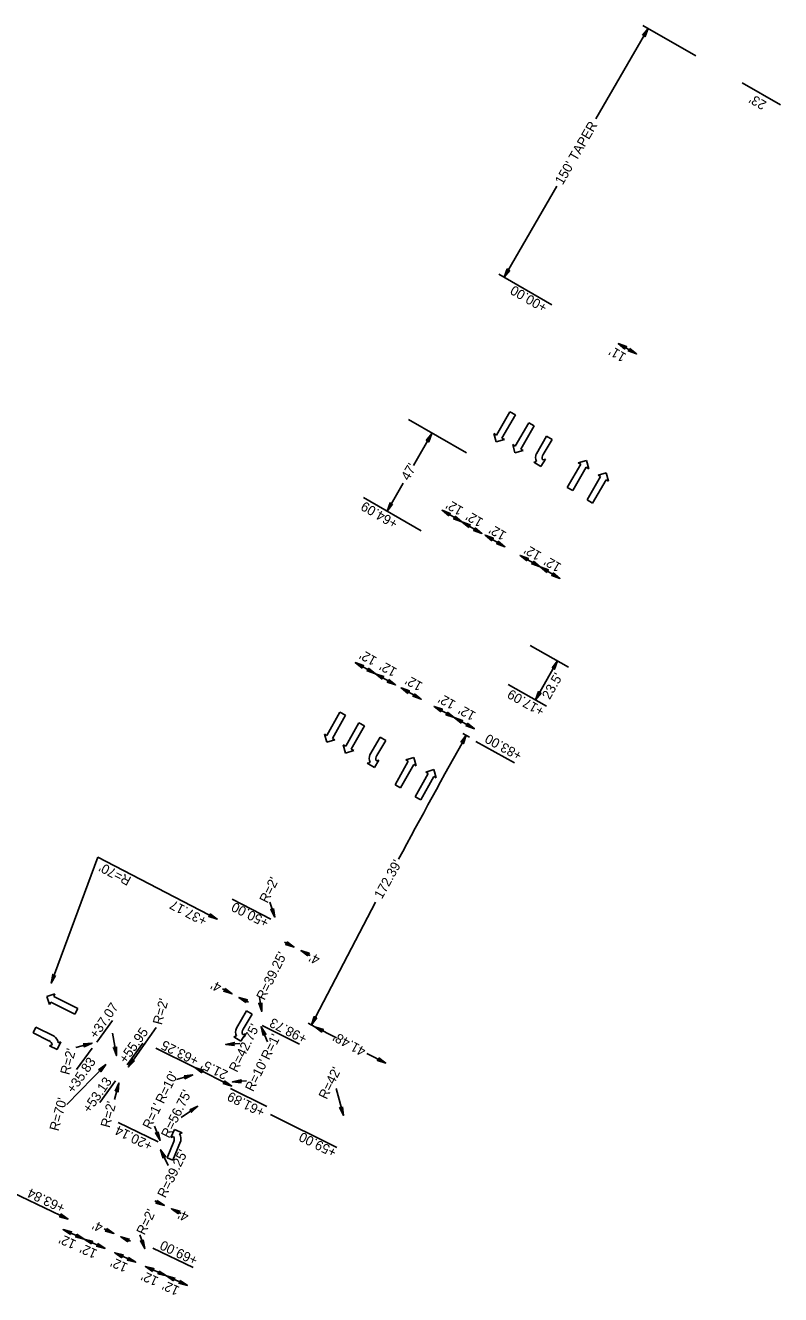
# Model space of a CAD drawing. Extents: x 2320991 to 2332664, y 598057 to 612602.
# Drawn here: x 2328874 to 2329267, y 607916 to 608578 of the extents above; entities that cross this region are included whole.
import ezdxf

# ---------------------------------------------------------------- set-up
doc = ezdxf.new("R2010")
doc.units = 0
for name, color, linetype in [('Prop Dimension', 7, 'Continuous'), ('Prop Dimension Text', 7, 'Continuous'), ('Prop Lane Arrow CELL', 7, 'Continuous'), ('Prop Terminator CELL', 7, 'Continuous')]:
    doc.layers.add(name, color=color, linetype=linetype)

msp = doc.modelspace()

# ---------------------------------------------------------------- linework, layer by layer
at = {"layer": 'Prop Dimension'}
for p, q in [((2329223.25, 608562.07), (2329195.67, 608578.01)), ((2329171.09, 608529.31), (2329198.34, 608576.46)), ((2329247.48, 608548.05), (2329267.44, 608536.61)), ((2329123.38, 608446.76), (2329150.83, 608494.25)), ((2329148.28, 608432.37), (2329120.61, 608448.36)), ((2329182.81, 608412.17), (2329192.38, 608406.74)), ((2329103.69, 608355.21), (2329073.58, 608372.62)), ((2329085.64, 608365.19), (2329076.05, 608348.63)), ((2329070.73, 608339.37), (2329062.32, 608324.84)), ((2329080.17, 608314.52), (2329050.06, 608331.92)), ((2329101.37, 608319.21), (2329090.98, 608325.22)), ((2329111.76, 608313.2), (2329101.37, 608319.21)), ((2329123.8, 608306.26), (2329113.41, 608312.27)), ((2329142.08, 608295.73), (2329131.69, 608301.73)), ((2329152.47, 608289.72), (2329142.08, 608295.73)), ((2329156.97, 608243.48), (2329136.96, 608254.79)), ((2329151.21, 608246.69), (2329139.71, 608226.39)), ((2329056.28, 608240.03), (2329045.8, 608245.87)), ((2329066.76, 608234.19), (2329056.28, 608240.03)), ((2329145.49, 608223.17), (2329125.43, 608234.51)), ((2329080.17, 608226.77), (2329069.69, 608232.61)), ((2329097.36, 608217.2), (2329086.88, 608223.04)), ((2329107.85, 608211.36), (2329097.36, 608217.2)), ((2329105.39, 608206.96), (2329101.89, 608208.9)), ((2329108.69, 608204.67), (2329128.73, 608193.52)), ((2328887.3, 608078.74), (2328911.68, 608144.36)), ((2328973.82, 608112.12), (2328911.68, 608144.36)), ((2329001.71, 608112.11), (2328981.67, 608122.58)), ((2329003.89, 608113.15), (2329001.28, 608120.91)), ((2329008.93, 608100.11), (2329013.86, 608097.56)), ((2329017.42, 608095.73), (2329022.34, 608093.19)), ((2328976.66, 608075.71), (2328981.6, 608073.17)), ((2328985.15, 608071.33), (2328990.07, 608068.79)), ((2328997, 608063.97), (2328995.84, 608071.31)), ((2328927.52, 608035.05), (2328941.98, 608055.64)), ((2328996.73, 608055.98), (2329000.08, 608048.07)), ((2328997.34, 608056.7), (2329016.68, 608046.86)), ((2329024.76, 608055.99), (2329021.19, 608057.81)), ((2329035.92, 608050.27), (2329024.76, 608055.99)), ((2328921.31, 608040.95), (2328919.33, 608052.61)), ((2328908.61, 608047.52), (2328900.07, 608045.23)), ((2328962.16, 608034.71), (2328941.93, 608044.83)), ((2328985.57, 608047.22), (2328978.24, 608046.79)), ((2329061.68, 608037.08), (2329051.83, 608042.12)), ((2328915.71, 608036.33), (2328895.51, 608015.54)), ((2328962.15, 608034.71), (2328981.38, 608025.1)), ((2328961.12, 608030.87), (2328952.58, 608028.57)), ((2328922.57, 608026.65), (2328920.27, 608018.11)), ((2328980.78, 608023.88), (2328999.73, 608014.41)), ((2328981.77, 608027.25), (2328989.12, 608027.74)), ((2329039.58, 608009.76), (2329035.78, 608023.87)), ((2328963.66, 608014.6), (2328955.03, 608008.77)), ((2329001.64, 608010.25), (2329036.09, 607993.06)), ((2328943, 607995.99), (2328922.25, 608006.15)), ((2328944.08, 607996.8), (2328941.07, 608004.18)), ((2328944.32, 607991.86), (2328948.3, 607983.7)), ((2328896.13, 607955.8), (2328832.86, 607985.72)), ((2328941.34, 607965.24), (2328946.35, 607962.85)), ((2328949.96, 607961.13), (2328954.96, 607958.74)), ((2328904.46, 607945.35), (2328893.51, 607950.27)), ((2328914.94, 607950.66), (2328919.96, 607948.27)), ((2328915.4, 607940.43), (2328904.46, 607945.35)), ((2328923.57, 607946.55), (2328928.57, 607944.17)), ((2328936.1, 607940.38), (2328933.47, 607947.49)), ((2328931.36, 607933.25), (2328920.42, 607938.17)), ((2328940.21, 607940.55), (2328961.3, 607930.49)), ((2328947.34, 607926.12), (2328936.4, 607931.04)), ((2328958.29, 607921.2), (2328947.34, 607926.12))]:
    msp.add_line(p, q, dxfattribs=at)
for start, end in [(150.90484, 151.75661), (152.04941, 152.88421)]:
    msp.add_arc((2333432.95, 605798.75), 4954.5, start, end, dxfattribs=at)
at = {"layer": 'Prop Dimension Text'}
for p, q in [((2328919.31, 608059.21), (2328911.18, 608048.01)), ((2328908.7, 608044.91), (2328900.57, 608033.71)), ((2328935.07, 608047.44), (2328926.94, 608036.24)), ((2328920.78, 608027.75), (2328912.64, 608016.55))]:
    msp.add_line(p, q, dxfattribs=at)
at = {"layer": 'Prop Lane Arrow CELL'}
for p, q in [((2329119.37, 608364.48), (2329126.41, 608376.58)), ((2329129.26, 608374.92), (2329122.22, 608362.82)), ((2329126.41, 608376.58), (2329129.26, 608374.92)), ((2329129.13, 608358.74), (2329136.17, 608370.84)), ((2329139.02, 608369.18), (2329131.98, 608357.08)), ((2329136.17, 608370.84), (2329139.02, 608369.18)), ((2329119.25, 608360.9), (2329118.07, 608365.23)), ((2329118.07, 608365.23), (2329119.37, 608364.48)), ((2329123.52, 608362.06), (2329119.25, 608360.9)), ((2329122.22, 608362.82), (2329123.52, 608362.06)), ((2329129.01, 608355.16), (2329127.83, 608359.49)), ((2329127.83, 608359.49), (2329129.13, 608358.74)), ((2329145.51, 608363.83), (2329140.15, 608354.74)), ((2329143.71, 608354.27), (2329148.35, 608362.16)), ((2329148.35, 608362.16), (2329145.51, 608363.83)), ((2329133.28, 608356.33), (2329129.01, 608355.16)), ((2329131.98, 608357.08), (2329133.28, 608356.33)), ((2329140.21, 608350.71), (2329138.77, 608350.33)), ((2329138.77, 608350.33), (2329142.54, 608348.06)), ((2329142.54, 608348.06), (2329144.87, 608351.91)), ((2329144.87, 608351.91), (2329143.43, 608351.54)), ((2329156.26, 608337.2), (2329163.3, 608349.3)), ((2329166.15, 608347.64), (2329159.11, 608335.54)), ((2329162, 608350.06), (2329166.27, 608351.22)), ((2329163.3, 608349.3), (2329162, 608350.06)), ((2329167.45, 608346.89), (2329166.15, 608347.64)), ((2329166.27, 608351.22), (2329167.45, 608346.89)), ((2329166.61, 608330.69), (2329173.65, 608342.79)), ((2329176.5, 608341.13), (2329169.46, 608329.03)), ((2329172.35, 608343.54), (2329176.61, 608344.71)), ((2329173.65, 608342.79), (2329172.35, 608343.54)), ((2329177.8, 608340.37), (2329176.5, 608341.13)), ((2329176.61, 608344.71), (2329177.8, 608340.37)), ((2329159.11, 608335.54), (2329156.26, 608337.2)), ((2329169.46, 608329.03), (2329166.61, 608330.69)), ((2329030.97, 608207.87), (2329037.81, 608220.08)), ((2329037.81, 608220.08), (2329040.69, 608218.47)), ((2329040.69, 608218.47), (2329033.85, 608206.26)), ((2329040.83, 608202.29), (2329047.66, 608214.51)), ((2329047.66, 608214.51), (2329050.54, 608212.9)), ((2329030.92, 608204.29), (2329029.66, 608208.6)), ((2329029.66, 608208.6), (2329030.97, 608207.87)), ((2329050.54, 608212.9), (2329043.71, 608200.68)), ((2329058.79, 608206.89), (2329053.43, 608197.8)), ((2329061.63, 608205.22), (2329058.79, 608206.89)), ((2329035.16, 608205.52), (2329030.92, 608204.29)), ((2329033.85, 608206.26), (2329035.16, 608205.52)), ((2329040.77, 608198.71), (2329039.52, 608203.03)), ((2329039.52, 608203.03), (2329040.83, 608202.29)), ((2329043.71, 608200.68), (2329045.01, 608199.95)), ((2329056.99, 608197.34), (2329061.63, 608205.22)), ((2329045.01, 608199.95), (2329040.77, 608198.71)), ((2329053.49, 608193.77), (2329052.05, 608193.39)), ((2329055.82, 608191.12), (2329058.14, 608194.97)), ((2329058.14, 608194.97), (2329056.71, 608194.6)), ((2329066.53, 608182.2), (2329073.37, 608194.42)), ((2329072.06, 608195.15), (2329076.31, 608196.39)), ((2329073.37, 608194.42), (2329072.06, 608195.15)), ((2329076.31, 608196.39), (2329077.56, 608192.08)), ((2329052.05, 608193.39), (2329055.82, 608191.12)), ((2329076.25, 608192.81), (2329069.41, 608180.59)), ((2329077.56, 608192.08), (2329076.25, 608192.81)), ((2329076.99, 608175.86), (2329083.83, 608188.08)), ((2329082.52, 608188.81), (2329086.76, 608190.05)), ((2329083.83, 608188.08), (2329082.52, 608188.81)), ((2329086.76, 608190.05), (2329088.02, 608185.74)), ((2329069.41, 608180.59), (2329066.53, 608182.2)), ((2329086.71, 608186.47), (2329079.87, 608174.25)), ((2329088.02, 608185.74), (2329086.71, 608186.47)), ((2329079.87, 608174.25), (2329076.99, 608175.86)), ((2328885.03, 608071.76), (2328889.28, 608073.21)), ((2328886.46, 608067.58), (2328885.03, 608071.76)), ((2328887.13, 608068.92), (2328886.46, 608067.58)), ((2328899.65, 608062.66), (2328887.13, 608068.92)), ((2328889.28, 608073.21), (2328888.61, 608071.87)), ((2328888.61, 608071.87), (2328901.13, 608065.61)), ((2328901.13, 608065.61), (2328899.65, 608062.66)), ((2328989.18, 608064.34), (2328983.82, 608055.25)), ((2328987.37, 608054.78), (2328992.02, 608062.66)), ((2328992.02, 608062.66), (2328989.18, 608064.34)), ((2328877.92, 608052.83), (2328879.39, 608055.79)), ((2328879.39, 608055.79), (2328888.84, 608051.09)), ((2328886.11, 608048.76), (2328877.92, 608052.83)), ((2328892.4, 608048.15), (2328890.49, 608044.19)), ((2328890.99, 608047.68), (2328892.4, 608048.15)), ((2328983.88, 608051.21), (2328982.44, 608050.84)), ((2328982.44, 608050.84), (2328986.2, 608048.56)), ((2328986.2, 608048.56), (2328988.53, 608052.41)), ((2328988.53, 608052.41), (2328987.09, 608052.04)), ((2328886.43, 608046.14), (2328887.84, 608046.62)), ((2328890.49, 608044.19), (2328886.43, 608046.14)), ((2328951.51, 608002.44), (2328949.72, 607998.31)), ((2328955.55, 608000.69), (2328951.51, 608002.44)), ((2328951.2, 607996.12), (2328947.67, 607987.68)), ((2328949.72, 607998.31), (2328951.1, 607998.87)), ((2328950.71, 607986.4), (2328954.78, 607996.14)), ((2328954.17, 608000.13), (2328955.55, 608000.69)), ((2328947.67, 607987.68), (2328950.71, 607986.4))]:
    msp.add_line(p, q, dxfattribs=at)
for centre, radius, start, end in [((2329145.01, 608352.8), 5.25, 158.16586, 203.47755), ((2329146.51, 608352.61), 3.27, 149.48978, 199.14796), ((2329058.29, 608195.86), 5.25, 158.16586, 203.47755), ((2329059.79, 608195.67), 3.27, 149.48978, 199.14796), ((2328988.68, 608053.3), 5.25, 158.16586, 203.47755), ((2328990.17, 608053.12), 3.27, 149.48978, 199.14796), ((2328884.67, 608045.84), 3.27, 13.92859, 63.58676), ((2328885.82, 608046.81), 5.25, 9.59899, 54.91069), ((2328948.19, 607997.38), 3.27, 337.31628, 26.97445), ((2328949.7, 607997.4), 5.25, 345.99235, 31.30404)]:
    msp.add_arc(centre, radius, start, end, dxfattribs=at)
at = {"layer": 'Prop Terminator CELL'}
for points in [[(2329195.42, 608572.95), (2329198.34, 608576.46), (2329196.77, 608572.14), (2329196.37, 608573.04)], [(2329126.3, 608450.27), (2329123.38, 608446.76), (2329124.95, 608451.08), (2329125.36, 608450.18)], [(2329186.34, 608409.27), (2329182.81, 608412.17), (2329187.14, 608410.63), (2329186.25, 608410.22)], [(2329188.85, 608409.63), (2329192.38, 608406.74), (2329188.05, 608408.28), (2329188.94, 608408.69)], [(2329082.71, 608361.69), (2329085.64, 608365.19), (2329084.07, 608360.88), (2329083.66, 608361.77)], [(2329065.24, 608328.35), (2329062.32, 608324.84), (2329063.89, 608329.16), (2329064.3, 608328.26)], [(2329094.49, 608322.29), (2329090.98, 608325.22), (2329095.3, 608323.64), (2329094.4, 608323.24)], [(2329097.86, 608322.13), (2329101.37, 608319.21), (2329097.05, 608320.78), (2329097.95, 608321.19)], [(2329104.88, 608316.29), (2329101.37, 608319.21), (2329105.69, 608317.64), (2329104.79, 608317.23)], [(2329108.25, 608316.13), (2329111.76, 608313.2), (2329107.44, 608314.78), (2329108.34, 608315.18)], [(2329116.92, 608309.34), (2329113.41, 608312.27), (2329117.73, 608310.69), (2329116.83, 608310.29)], [(2329120.29, 608309.18), (2329123.8, 608306.26), (2329119.48, 608307.83), (2329120.38, 608308.24)], [(2329135.2, 608298.81), (2329131.69, 608301.73), (2329136.01, 608300.16), (2329135.11, 608299.76)], [(2329138.58, 608298.65), (2329142.08, 608295.73), (2329137.77, 608297.3), (2329138.66, 608297.7)], [(2329145.59, 608292.8), (2329142.08, 608295.73), (2329146.4, 608294.15), (2329145.5, 608293.75)], [(2329148.96, 608292.64), (2329152.47, 608289.72), (2329148.15, 608291.29), (2329149.05, 608291.7)], [(2329148.31, 608243.16), (2329151.21, 608246.69), (2329149.67, 608242.36), (2329149.26, 608243.26)], [(2329049.35, 608243), (2329045.8, 608245.87), (2329050.14, 608244.37), (2329049.25, 608243.95)], [(2329052.73, 608242.9), (2329056.28, 608240.03), (2329051.94, 608241.54), (2329052.83, 608241.95)], [(2329059.84, 608237.16), (2329056.28, 608240.03), (2329060.62, 608238.53), (2329059.73, 608238.11)], [(2329063.21, 608237.06), (2329066.76, 608234.19), (2329062.42, 608235.7), (2329063.31, 608236.11)], [(2329073.24, 608229.74), (2329069.69, 608232.61), (2329074.03, 608231.1), (2329073.14, 608230.68)], [(2329076.62, 608229.63), (2329080.17, 608226.77), (2329075.83, 608228.27), (2329076.72, 608228.69)], [(2329142.6, 608229.93), (2329139.71, 608226.39), (2329141.24, 608230.72), (2329141.66, 608229.83)], [(2329090.43, 608220.17), (2329086.88, 608223.04), (2329091.22, 608221.54), (2329090.33, 608221.12)], [(2329093.81, 608220.07), (2329097.36, 608217.2), (2329093.02, 608218.7), (2329093.91, 608219.12)], [(2329100.92, 608214.33), (2329097.36, 608217.2), (2329101.71, 608215.7), (2329100.81, 608215.28)], [(2329104.29, 608214.23), (2329107.85, 608211.36), (2329103.5, 608212.86), (2329104.4, 608213.28)], [(2329100.77, 608204.37), (2329103.64, 608207.93), (2329102.14, 608203.59), (2329101.72, 608204.48)], [(2328970.18, 608114.88), (2328973.82, 608112.12), (2328969.43, 608113.5), (2328970.31, 608113.94)], [(2329003.19, 608117.66), (2329003.89, 608113.15), (2329001.69, 608117.18), (2329002.63, 608116.89)], [(2329010.22, 608100.31), (2329013.86, 608097.56), (2329009.47, 608098.92), (2329010.35, 608099.37)], [(2329021.06, 608092.97), (2329017.42, 608095.73), (2329021.81, 608094.36), (2329020.93, 608093.92)], [(2328889.59, 608082.69), (2328887.3, 608078.74), (2328888.12, 608083.26), (2328888.67, 608082.45)], [(2328889.59, 608082.69), (2328887.3, 608078.74), (2328888.12, 608083.26), (2328888.67, 608082.45)], [(2328977.95, 608075.92), (2328981.6, 608073.17), (2328977.21, 608074.53), (2328978.09, 608074.98)], [(2328988.8, 608068.58), (2328985.15, 608071.33), (2328989.54, 608069.97), (2328988.66, 608069.52)], [(2328997.06, 608068.53), (2328997, 608063.97), (2328995.5, 608068.31), (2328996.38, 608067.87)], [(2329025.75, 608060.61), (2329023.01, 608056.96), (2329024.36, 608061.35), (2329024.81, 608060.48)], [(2328997.78, 608051.53), (2328996.73, 608055.98), (2328999.23, 608052.12), (2328998.27, 608052.34)], [(2329028.41, 608053.24), (2329024.76, 608055.99), (2329029.15, 608054.64), (2329028.27, 608054.19)], [(2328904.06, 608047.1), (2328908.61, 608047.52), (2328904.45, 608045.57), (2328904.79, 608046.5)], [(2328921.32, 608045.52), (2328921.31, 608040.95), (2328919.76, 608045.28), (2328920.65, 608044.85)], [(2328982.78, 608046.28), (2328978.24, 608046.79), (2328982.71, 608047.86), (2328982.19, 608047.02)], [(2328912.01, 608033.64), (2328915.71, 608036.33), (2328913.13, 608032.52), (2328912.95, 608033.49)], [(2328930.74, 608038.29), (2328927.52, 608035.05), (2328929.47, 608039.22), (2328929.79, 608038.29)], [(2328965.83, 608032.01), (2328962.15, 608034.71), (2328966.56, 608033.41), (2328965.69, 608032.95)], [(2329058.03, 608039.82), (2329061.68, 608037.08), (2329057.28, 608038.43), (2329058.16, 608038.88)], [(2328956.57, 608030.45), (2328961.12, 608030.87), (2328956.96, 608028.92), (2328957.31, 608029.84)], [(2328986.32, 608026.78), (2328981.77, 608027.25), (2328986.24, 608028.35), (2328985.72, 608027.52)], [(2328920.65, 608022.5), (2328922.57, 608026.65), (2328922.17, 608022.07), (2328921.54, 608022.83)], [(2328977.7, 608027.8), (2328981.38, 608025.1), (2328976.98, 608026.41), (2328977.85, 608026.86)], [(2328959.49, 608012.73), (2328963.66, 608014.6), (2328960.36, 608011.41), (2328960.38, 608012.39)], [(2329039.16, 608014.31), (2329039.58, 608009.76), (2329037.63, 608013.92), (2329038.55, 608013.58)], [(2328943.1, 608001.26), (2328944.08, 607996.8), (2328941.63, 608000.68), (2328942.59, 608000.45)], [(2328945.6, 607987.48), (2328944.32, 607991.86), (2328947.02, 607988.15), (2328946.05, 607988.31)], [(2328942.62, 607965.48), (2328946.35, 607962.85), (2328941.92, 607964.07), (2328942.78, 607964.55)], [(2328892.39, 607958.43), (2328896.13, 607955.8), (2328891.7, 607957.01), (2328892.56, 607957.49)], [(2328953.69, 607958.49), (2328949.96, 607961.13), (2328954.39, 607959.9), (2328953.53, 607959.43)], [(2328897.3, 607947.72), (2328893.51, 607950.27), (2328897.97, 607949.15), (2328897.12, 607948.65)], [(2328916.23, 607950.91), (2328919.96, 607948.27), (2328915.53, 607949.5), (2328916.39, 607949.97)], [(2328900.67, 607947.91), (2328904.46, 607945.35), (2328900, 607946.48), (2328900.85, 607946.97)], [(2328908.24, 607942.8), (2328904.46, 607945.35), (2328908.91, 607944.23), (2328908.06, 607943.73)], [(2328911.62, 607942.98), (2328915.4, 607940.43), (2328910.95, 607941.56), (2328911.8, 607942.05)], [(2328927.3, 607943.91), (2328923.57, 607946.55), (2328928, 607945.32), (2328927.13, 607944.85)], [(2328935.27, 607944.87), (2328936.1, 607940.38), (2328933.78, 607944.35), (2328934.73, 607944.09)], [(2328924.2, 607935.61), (2328920.42, 607938.17), (2328924.87, 607937.04), (2328924.02, 607936.55)], [(2328927.58, 607935.8), (2328931.36, 607933.25), (2328926.91, 607934.37), (2328927.76, 607934.87)], [(2328940.18, 607928.49), (2328936.4, 607931.04), (2328940.85, 607929.92), (2328940, 607929.42)], [(2328943.56, 607928.67), (2328947.34, 607926.12), (2328942.89, 607927.25), (2328943.74, 607927.74)], [(2328951.13, 607923.57), (2328947.34, 607926.12), (2328951.8, 607924.99), (2328950.94, 607924.5)], [(2328954.5, 607923.75), (2328958.29, 607921.2), (2328953.83, 607922.33), (2328954.68, 607922.82)]]:
    msp.add_lwpolyline(points, close=True, dxfattribs=at)

# ---------------------------------------------------------------- texts
at = {"layer": 'Prop Dimension'}
for s, rotation, p in [('+00.00', 149.97374, (2329146.34, 608432.37)), ('+83.00', 150.90934, (2329133.22, 608198.86)), ('+37.17', 152.48009, (2328969.11, 608112.75)), ('+50.00', 153.02427, (2329001.29, 608111.83)), ('+37.07', 55.23206, (2328910.86, 608049.36)), ('+55.95', 54.70744, (2328926.27, 608036.48)), ('+98.73', 153.02427, (2329021.17, 608051.43)), ('+63.25', 153.42807, (2328964.7, 608039.93)), ('+35.83', 55.10685, (2328899.02, 608020.92)), ('+53.13', 55.10685, (2328907.39, 608010.62)), ('+61.89', 153.44365, (2328999.19, 608013.16)), ('+20.14', 153.9199, (2328940.72, 607995.6)), ('+59.00', 153.47709, (2329036.56, 607992.11)), ('+63.84', 154.69292, (2328895.09, 607963.19)), ('+69.00', 154.51759, (2328964.21, 607935.92))]:
    msp.add_text(s, height=5, rotation=rotation, dxfattribs=at).set_placement(p)
at = {"layer": 'Prop Dimension Text'}
for s, rotation, p in [("23'", 149.8653, (2329260.54, 608537.96)), ("150' TAPER", 59.97374, (2329153.85, 608494.49)), ("11'", 149.8653, (2329187.44, 608406.5)), ("47'", 59.93452, (2329073.58, 608340.33)), ('+64.09', 149.76572, (2329068.48, 608319.68)), ("12'", 149.96697, (2329102.52, 608326.49)), ("12'", 149.96697, (2329112.91, 608320.48)), ("12'", 149.96697, (2329124.95, 608313.54)), ("12'", 149.96697, (2329143.23, 608303)), ("12'", 149.96697, (2329153.62, 608297)), ("12'", 150.87983, (2329057.45, 608248.31)), ("12'", 150.87983, (2329067.94, 608242.47)), ("23.5'", 60.47808, (2329147.1, 608226.21)), ("12'", 150.87983, (2329081.34, 608235.04)), ("12'", 150.87983, (2329098.53, 608225.47)), ('+17.09', 150.30929, (2329144.88, 608221.91)), ("12'", 150.87983, (2329109.02, 608219.63)), ("R=70'", 152.53024, (2328929.44, 608133.77)), ("172.39'", 60.87983, (2329059.65, 608122.24)), ("R=2'", 63.72272, (2329000, 608120.09)), ("R=39.25'", 63.72272, (2328998.41, 608069.48)), ("4'", 152.71227, (2329027.88, 608092.51)), ("4'", 152.71227, (2328976.61, 608078.16)), ("R=2'", 74.94844, (2328944.94, 608056.68)), ("R=42.75'", 63.72272, (2328984.15, 608031.94)), ("R=1'", 63.72272, (2329000.84, 608038.33)), ("41.48'", 150.87983, (2329051.74, 608044.65)), ("R=2'", 74.94844, (2328896.7, 608030.61)), ("21.5'", 153.66805, (2328979.83, 608032.65)), ("R=10'", 63.72272, (2328992.56, 608021.82)), ("R=42'", 63.72272, (2329030.86, 608017.8)), ("R=10'", 63.72272, (2328945.86, 608015.49)), ("R=56.75'", 63.72272, (2328948.76, 607997.55)), ("R=70'", 74.94844, (2328891.09, 608001.33)), ("R=2'", 74.94844, (2328917.75, 608003.06)), ("R=1'", 63.72272, (2328939.13, 608002.21)), ("R=39.25'", 63.72272, (2328946.82, 607966.38)), ("R=2'", 63.72272, (2328935.92, 607947.05)), ("4'", 154.51561, (2328959.5, 607958.6)), ("4'", 154.51561, (2328914.81, 607953.1)), ("12'", 155.78872, (2328900.79, 607944.39)), ("12'", 155.78872, (2328911.73, 607939.47)), ("12'", 155.78872, (2328927.69, 607932.28)), ("12'", 155.78872, (2328943.67, 607925.16)), ("12'", 155.78872, (2328954.62, 607920.24))]:
    msp.add_text(s, height=5, rotation=rotation, dxfattribs=at).set_placement(p)

doc.saveas('drawing.dxf')
